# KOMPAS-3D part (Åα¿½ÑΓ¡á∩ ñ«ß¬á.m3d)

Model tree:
1. Эскиз:1
2. Операция выдавливания:1
     Расстояние 1 = 5
3. Эскиз:4
4. Вырезать элемент выдавливания:2
     Расстояние 2 = 59.25; Расстояние 1 = 59.25
5. Эскиз:5
6. Вырезать элемент выдавливания:3
     Расстояние 1 = 3.5
7. Фаска:1
     Угол = 45; Длина 1 = 2; Длина 2 = 2
8. Эскиз:6
9. Операция выдавливания:2
     Расстояние 1 = 61; Расстояние 2 = 61
10. Скругление:1
     Радиус = 0.5
11. Скругление:2
     Радиус = 0.5
12. Фаска:3
     Угол = 45; Длина 1 = 1.4; Длина 2 = 1.4
13. Эскиз:7
14. Вырезать элемент выдавливания:4
     Расстояние 2 = 61; Расстояние 1 = 61
15. Скругление:5
     Радиус = 0.5
16. Скругление:6
     Радиус = 0.5
17. Скругление:7
     Радиус = 0.5
18. Скругление:8
     Радиус = 0.5
19. Скругление:9
     Радиус = 0.5
20. Скругление:10
     Радиус = 0.5
21. Скругление:11
     Радиус = 0.5
22. Скругление:12
     Радиус = 0.5
